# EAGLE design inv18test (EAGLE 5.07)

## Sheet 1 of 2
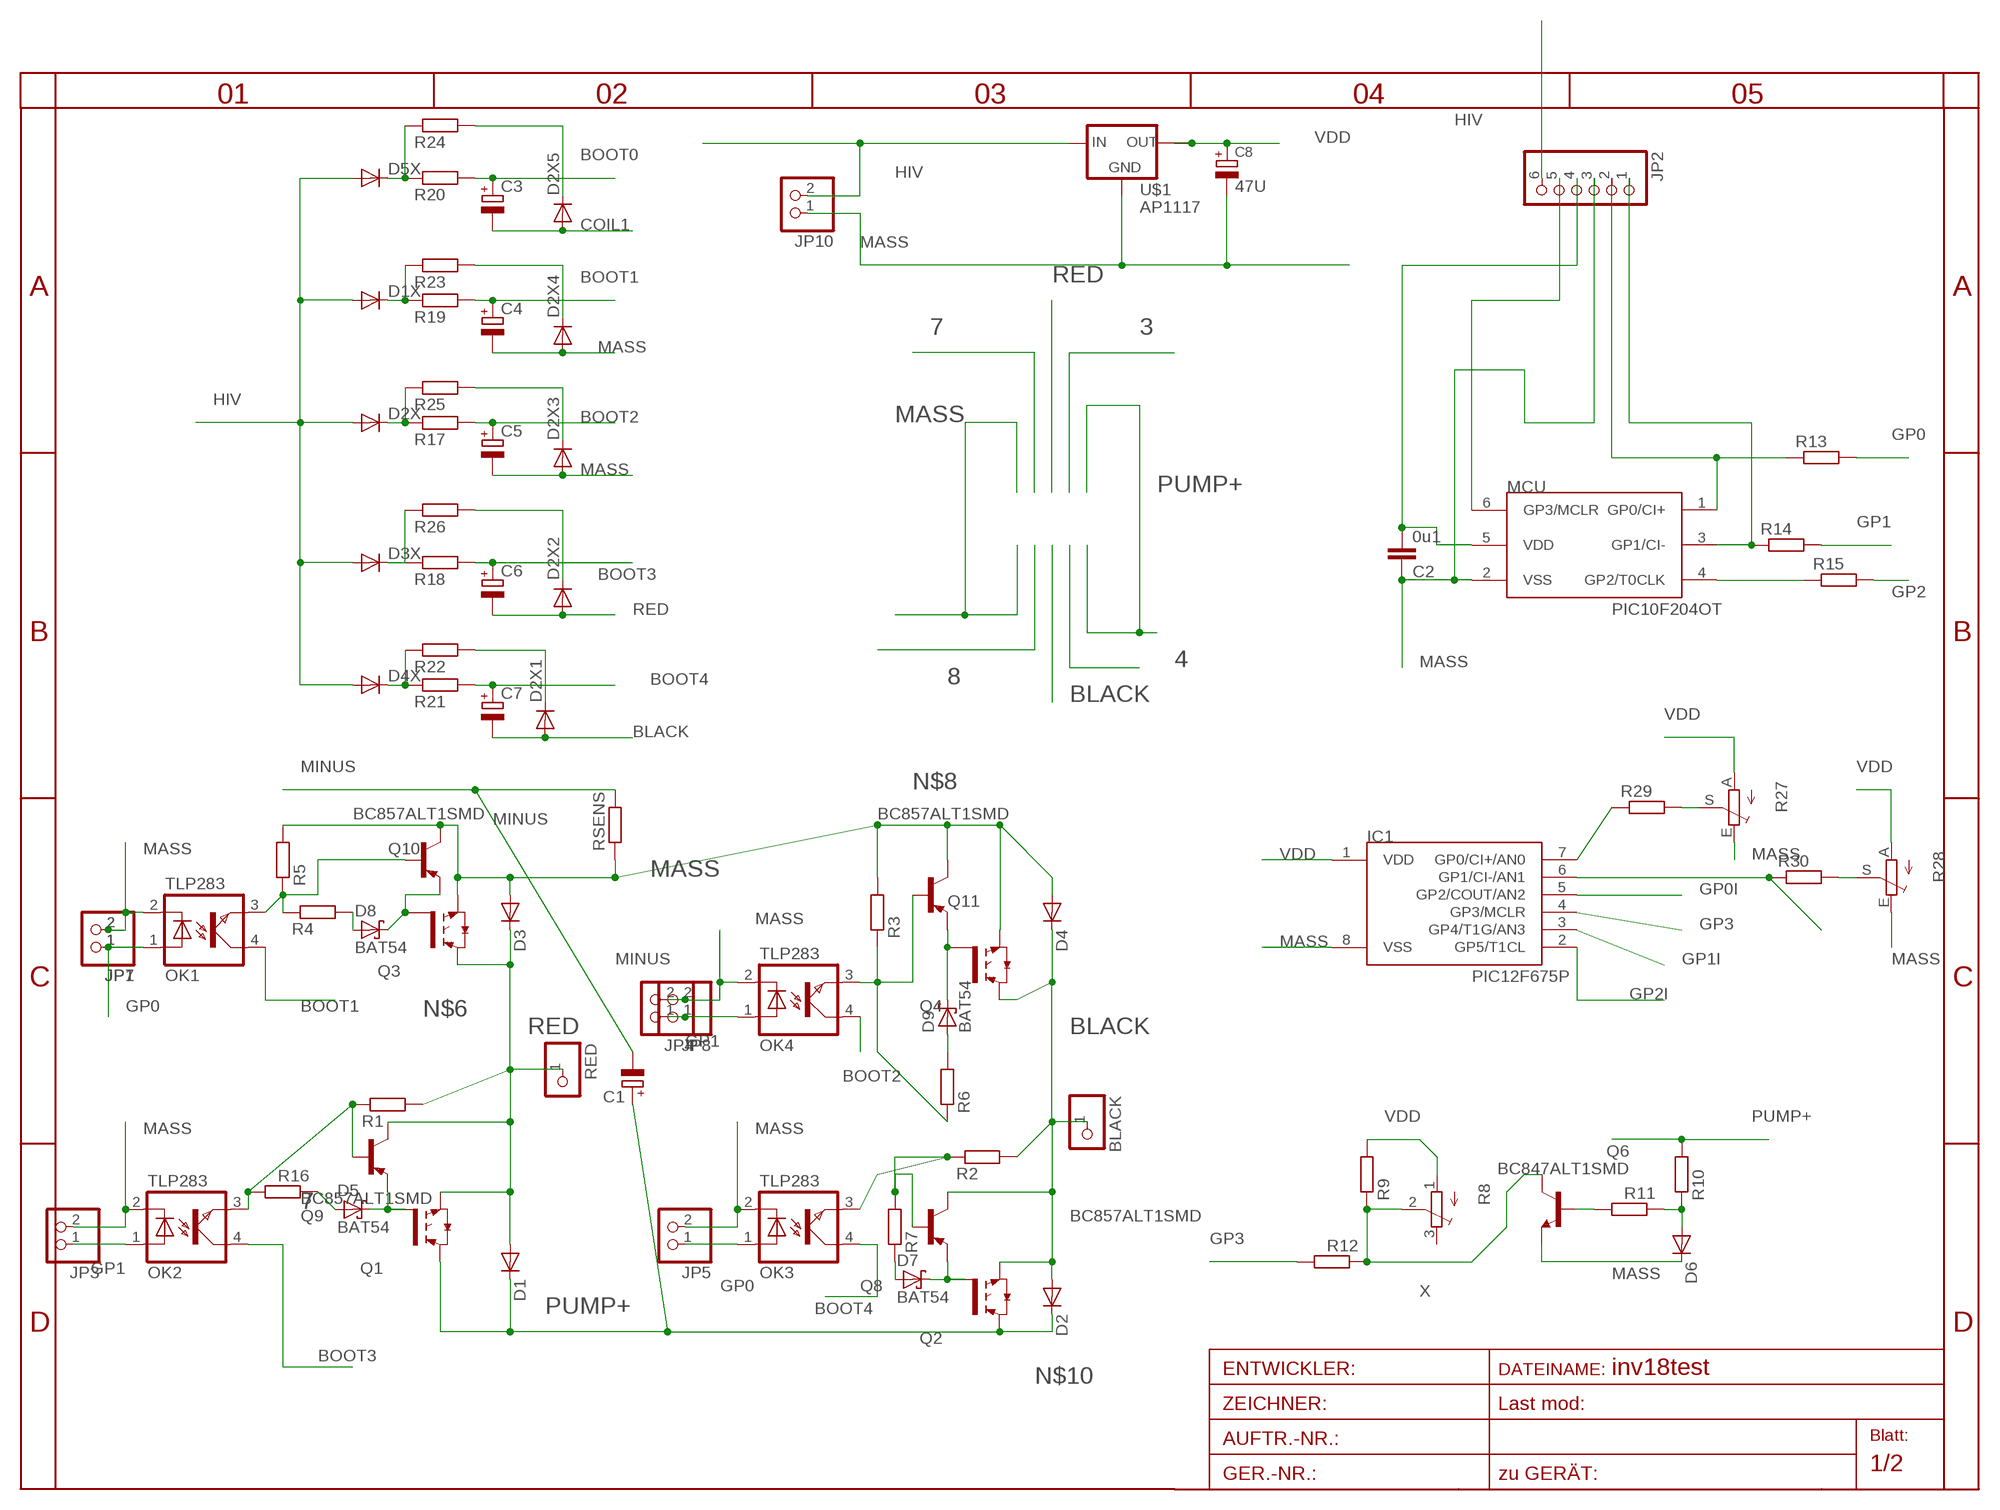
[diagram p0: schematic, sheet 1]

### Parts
BLACK  PINHD-1X14.5MM  [1X4MM5]
C1  CPOL-EUE5-13  [E5-13]
C2  0u1  C-EUC0805  [C0805]
C3  CPOL-EUC  [PANASONIC_C]
C4  CPOL-EUC  [PANASONIC_C]
C5  CPOL-EUC  [PANASONIC_C]
C6  CPOL-EUC  [PANASONIC_C]
C7  CPOL-EUC  [PANASONIC_C]
C8  47U  CPOL-EUC  [PANASONIC_C]
D1  DIODE-SMC  [SMC]
D1X  DIODE-SMA-DO214  [SMA-DO214AC]
D2  DIODE-SMC  [SMC]
D2X  DIODE-SMA-DO214  [SMA-DO214AC]
D2X1  DIODE-MINIMELF  [MINIMELF]
D2X2  DIODE-MINIMELF  [MINIMELF]
D2X3  DIODE-MINIMELF  [MINIMELF]
D2X4  DIODE-MINIMELF  [MINIMELF]
D2X5  DIODE-MINIMELF  [MINIMELF]
D3  DIODE-SMC  [SMC]
D3X  DIODE-SMA-DO214  [SMA-DO214AC]
D4  DIODE-SMC  [SMC]
D4X  DIODE-SMA-DO214  [SMA-DO214AC]
D5  BAT54  [SOT23]
D5X  DIODE-SMA-DO214  [SMA-DO214AC]
D6  DIODE-MINIMELF  [MINIMELF]
D7  BAT54  [SOT23]
D8  BAT54  [SOT23]
D9  BAT54  [SOT23]
IC1  PIC12F675P  [DIL8]
JP1  PINHD-1X2STR  [1X02]
JP2  PINHD-1X6  [1X06BOX]
JP3  PINHD-1X2STR  [1X02]
JP4  PINHD-1X2STR  [1X02]
JP5  PINHD-1X2STR  [1X02]
JP7  PINHD-1X2STR  [1X02]
JP8  PINHD-1X2STR  [1X02]
JP10  PINHD-1X2STR  [1X02]
MCU  PIC10F204OT  [SOT23-6]
OK1  TLP283  [MINI-FLAT-4]
OK2  TLP283  [MINI-FLAT-4]
OK3  TLP283  [MINI-FLAT-4]
OK4  TLP283  [MINI-FLAT-4]
Q1  IRG4BC15UD-S  [D2PACK]
Q2  IRG4BC15UD-S  [D2PACK]
Q3  IRG4BC15UD-S  [D2PACK]
Q4  IRG4BC15UD-S  [D2PACK]
Q6  BC847ALT1SMD  [SOT23]
Q8  BC857ALT1SMD  [SOT23-BEC]
Q9  BC857ALT1SMD  [SOT23-BEC]
Q10  BC857ALT1SMD  [SOT23-BEC]
Q11  BC857ALT1SMD  [SOT23-BEC]
R1  R-EU_R1206  [R1206]
R2  R-EU_R1206  [R1206]
R3  R-EU_R1206  [R1206]
R4  R-EU_R1206  [R1206]
R5  R-EU_R1206  [R1206]
R6  R-EU_R1206  [R1206]
R7  R-EU_R1206  [R1206]
R8  TRIM_EU-3223W  [3223W]
R9  R-EU_R1206  [R1206]
R10  R-EU_R1206  [R1206]
R11  R-EU_R1206  [R1206]
R12  R-EU_R1206  [R1206]
R13  R-EU_R0805  [R0805]
R14  R-EU_0207/10  [0207/10]
R15  R-EU_R0805  [R0805]
R16  R-EU_R1206  [R1206]
R17  R-EU_R1206  [R1206]
R18  R-EU_R1206  [R1206]
R19  R-EU_R1206  [R1206]
R20  R-EU_R1206  [R1206]
R21  R-EU_R1206  [R1206]
R22  R-EU_R1206  [R1206]
R23  R-EU_R1206  [R1206]
R24  R-EU_R1206  [R1206]
R25  R-EU_R1206  [R1206]
R26  R-EU_R1206  [R1206]
R27  TRIM_EU-RAND160  [RANDL]
R28  TRIM_EU-RAND160  [RANDL]
R29  R-EU_0207/30  [0207/30]
R30  R-EU_R0805  [R0805]
RED  PINHD-1X14.5MM  [1X4MM5]
RSENS  R-EU_CERAM50  [CERAM50]
U$1  AP1117  [SOT223]

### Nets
3: OK1.3(EMIT) Q10.B R4.1 R5.1
4: OK3.3(EMIT) Q8.B R2.1 R7.2
7: OK2.3(EMIT) Q9.B R1.1 R16.2
BLACK: BLACK.1 C7.- D2.A D2X1.A D4.C Q2.3(E) Q4.2(C) Q8.C R2.2
BOOT0: C3.+ R20.2 ; also sheet 2
BOOT1: C4.+ OK1.4(COL) R19.2
BOOT2: C5.+ OK4.4(COL) R17.2
BOOT3: C6.+ OK2.4(COL) R18.2
BOOT4: C7.+ OK3.4(COL) R21.2
COIL1: C3.- D2X5.A ; also sheet 2
GP0: JP1.1 JP5.1 JP7.1 OK1.1(A) OK3.1(A) R13.2
GP0I: IC1.5(GP2/COUT/AN2) JP2.2 MCU.1(GP0/CI+) R13.1
GP1: JP3.1 JP4.1 JP8.1 OK2.1(A) OK4.1(A) R14.2
GP1I: IC1.3(GP4/T1G/AN3) JP2.1 MCU.3(GP1/CI-) R14.1
GP2: R15.2 ; also sheet 2
GP2I: IC1.2(GP5/T1CL) MCU.4(GP2/T0CLK) R15.1
GP3: IC1.4(GP3/MCLR) JP2.5 MCU.6(GP3/MCLR) R12.2
HIV: D1X.A D2X.A D3X.A D4X.A D5X.A JP2.6 JP10.2 U$1.3(IN) ; also sheet 2
MASS: C2.1 C4.- C5.- C8.- D2X3.A D2X4.A D3.A D4.A D6.C IC1.8(VSS) JP1.2 JP2.3 JP3.2 JP4.2 JP5.2 JP7.2 JP8.2 JP10.1 MCU.2(VSS) OK1.2(C) OK2.2(C) OK3.2(C) OK4.2(C) Q3.3(E) Q4.3(E) Q6.2(E) Q10.C Q11.C R3.2 R5.2 R27.E R28.E RSENS.1 U$1.1(GND) ; also sheet 2
MINUS: C1.- RSENS.2 ; also sheet 2
N$2: D8.1(A) R4.2
N$4: D6.A R10.1 R11.1
N$5: Q6.1(B) R11.2
N$6: D8.3(C) Q3.1(G) Q10.E
N$7: D9.3(C) Q4.1(G) Q11.E
N$8: OK4.3(EMIT) Q11.B R3.1 R6.1
N$9: D9.1(A) R6.2
N$10: D7.3(C) Q2.1(G) Q8.E
N$11: D7.1(A) R7.1
N$12: D5.1(A) R16.1
N$13: D3X.K(C) R18.1 R26.1
N$14: D5.3(C) Q1.1(G) Q9.E
N$15: D4X.K(C) R21.1 R22.1
N$16: D2X.K(C) R17.1 R25.1
N$17: D1X.K(C) R19.1 R23.1
N$18: D5X.K(C) R20.1 R24.1
N$19: D2X1.C R22.2
N$20: D2X5.C R24.2
N$21: D2X4.C R23.2
N$22: D2X2.C R26.2
N$23: D2X3.C R25.2
N$24: R28.S R30.2
N$31: IC1.6(GP1/CI-/AN1) R30.1
N$34: R27.S R29.2
N$35: IC1.7(GP0/CI+/AN0) R29.1
PUMP+: C1.+ D1.C D2.C Q1.2(C) Q2.2(C) R10.2 ; also sheet 2
RED: C6.- D1.A D2X2.A D3.C Q1.3(E) Q3.2(C) Q9.C R1.2 RED.1
VDD: C2.2 C8.+ IC1.1(VDD) JP2.4 MCU.5(VDD) R8.1(A) R9.2 R27.A R28.A U$1.2(OUT) U$1.4(TAB)
X: Q6.3(C) R8.2(S) R9.1 R12.1
Unconnected: R8.3(E)

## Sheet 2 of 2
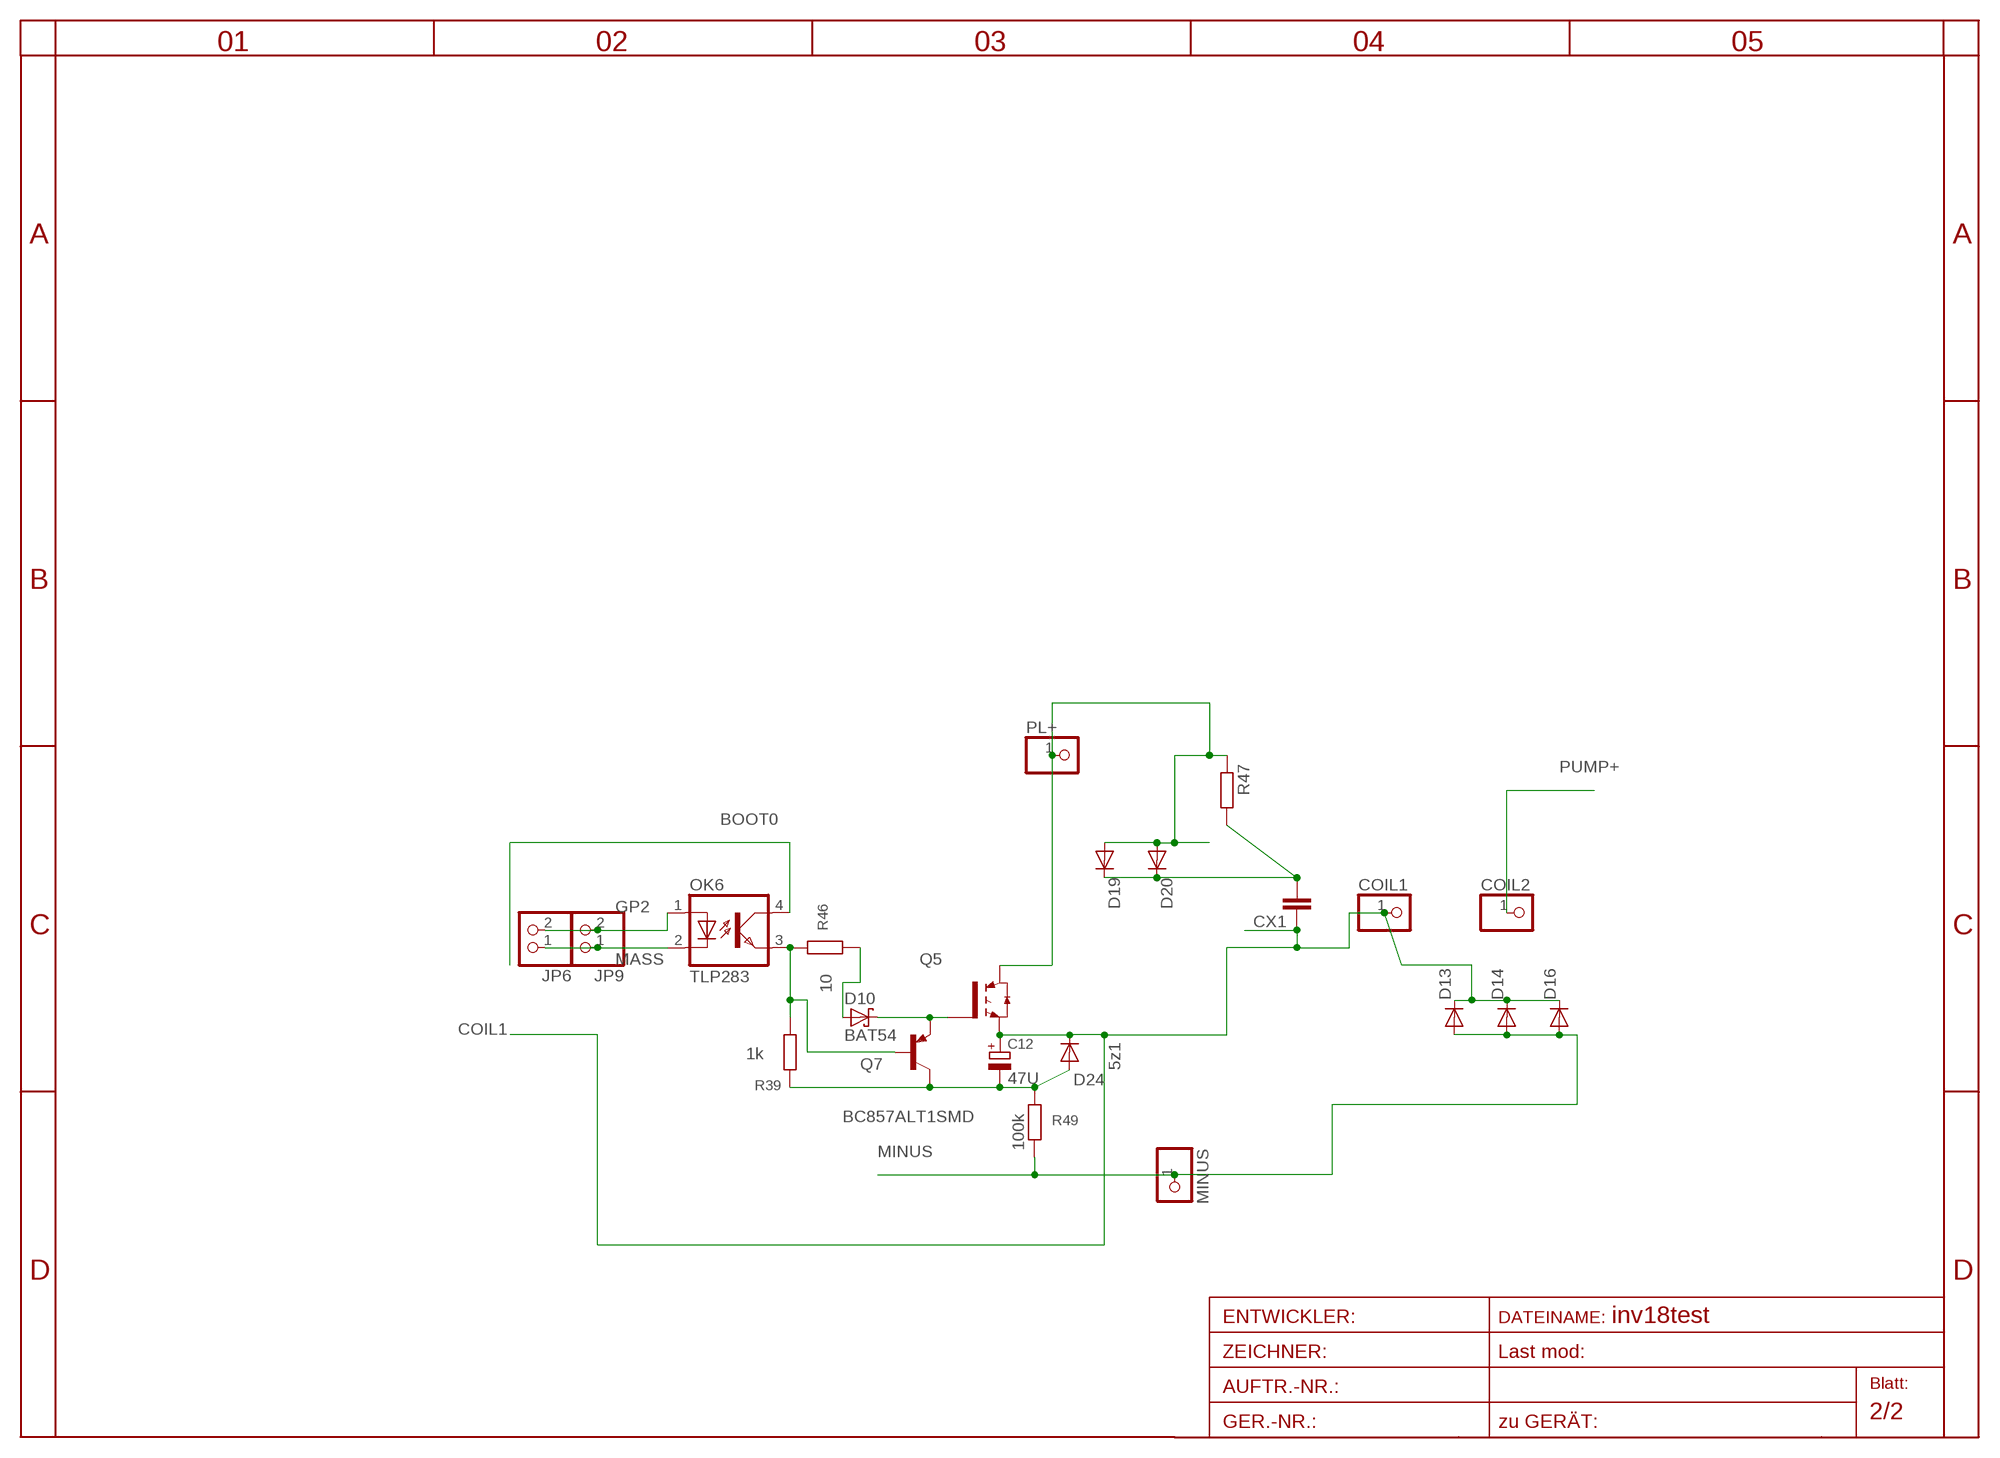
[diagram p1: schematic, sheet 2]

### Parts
C12  47U  CPOL-EUC  [PANASONIC_C]
COIL1  PINHD-1X14.5MM  [1X4MM5]
COIL2  PINHD-1X14.5MM  [1X4MM5]
CX1  CXXC22B10  [XC22B10]
D10  BAT54  [SOT23]
D13  DIODE-SMC  [SMC]
D14  DIODE-SMC  [SMC]
D16  DIODE-SMC  [SMC]
D19  DIODE-SMC  [SMC]
D20  DIODE-SMC  [SMC]
D24  5z1  DIODE-MINIMELF  [MINIMELF]
JP6  PINHD-1X2STR  [1X02]
JP9  PINHD-1X2STR  [1X02]
MINUS  PINHD-1X14.5MM  [1X4MM5]
OK6  TLP283  [MINI-FLAT-4]
PL+  PINHD-1X14.5MM  [1X4MM5]
Q5  IRG4BC15UD-S  [D2PACK]
Q7  BC857ALT1SMD  [SOT23-BEC]
R39  1k  R-EU_R1206  [R1206]
R46  10  R-EU_R1206  [R1206]
R47  R-EU_0207/5V  [0207/5V]
R49  100k  R-EU_R1206  [R1206]

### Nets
BATT-: C12.- D24.A Q7.C R39.1 R49.2
BOOT0: OK6.4(COL) ; also sheet 1
COIL1: C12.+ COIL1.1 CX1.1 D13.C D14.C D16.C D24.C Q5.3(E) ; also sheet 1
GP2: JP6.2 JP9.2 OK6.1(A) ; also sheet 1
HIV: D19.A D20.A PL+.1 Q5.2(C) R47.1 ; also sheet 1
MASS: JP6.1 JP9.1 OK6.2(C) ; also sheet 1
MINUS: D13.A D14.A D16.A MINUS.1 R49.1 ; also sheet 1
N$1: D10.3(C) Q5.1(G) Q7.E
N$3: D10.1(A) R46.1
N$43: OK6.3(EMIT) Q7.B R39.2 R46.2
PUMP+: COIL2.1 ; also sheet 1
SNUB: CX1.2 D19.C D20.C R47.2

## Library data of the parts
BLACK COIL1 COIL2 MINUS PL+ RED = pinhead:PINHD-1X1: PIN HEADER
C1 C3-C7 = rcl:CPOL-EU: POLARIZED CAPACITOR, European symbol
C2 = rcl:C-EU: CAPACITOR, European symbol
C8 C12 = rcl-2:CPOL-EU: POLARIZED CAPACITOR, European symbol
CX1 = rcl:CX: X CAPACITOR
D1 D1X D2 D2X D2X1-D2X5 D3 D3X D4 D4X D5X D6 D13 D14 D16 D19 D20 D24 = diode:DIODE-: DIODE
D5 D7-D10 = diode:BAT54: Schottky Diodes
IC1 = microchip-5:PIC12F6*: uPC nW 1k Program Flash memory 2x Timer Comparator 10b A/D converter/ 4xIN
JP1 JP3-JP10 = pinhead:PINHD-1X2: PIN HEADER
JP2 = pinhead:PINHD-1X6: PIN HEADER
MCU = microchip-3:PIC10F2*: uPC nW 0,25/0,5k Program Flash memory Comparator
OK1-OK4 OK6 = optocoupler:TLP283: TOSHIBA PHOTOCOUPLER GaAs IRED & PHOTO-TRANSISTOR Source: http://www.semicon.toshiba.co.jp/td/en/Opto/Photocoupler/en_20050928_TLP283_datasheet.pdf
Q1-Q5 = transistor-power:IRG4BC15UD-: INSULATED GATE BIPOLAR TRANSISTOR WITH ULTRAFAST SOFT RECOVERY DIODE
Q6 = transistor-npn:BC847*: NPN Transistor
Q7-Q11 = transistor-pnp:BC857*: PNP Transistror
R1-R7 R9-R12 R16-R26 R47 RSENS = rcl:R-EU_: RESISTOR, European symbol
R8 R27 R28 = pot:TRIM_EU-: POTENTIOMETER
R13-R15 R29 R30 R39 R46 R49 = rcl-2:R-EU_: RESISTOR, European symbol
U$1 = v-reg:AP1117

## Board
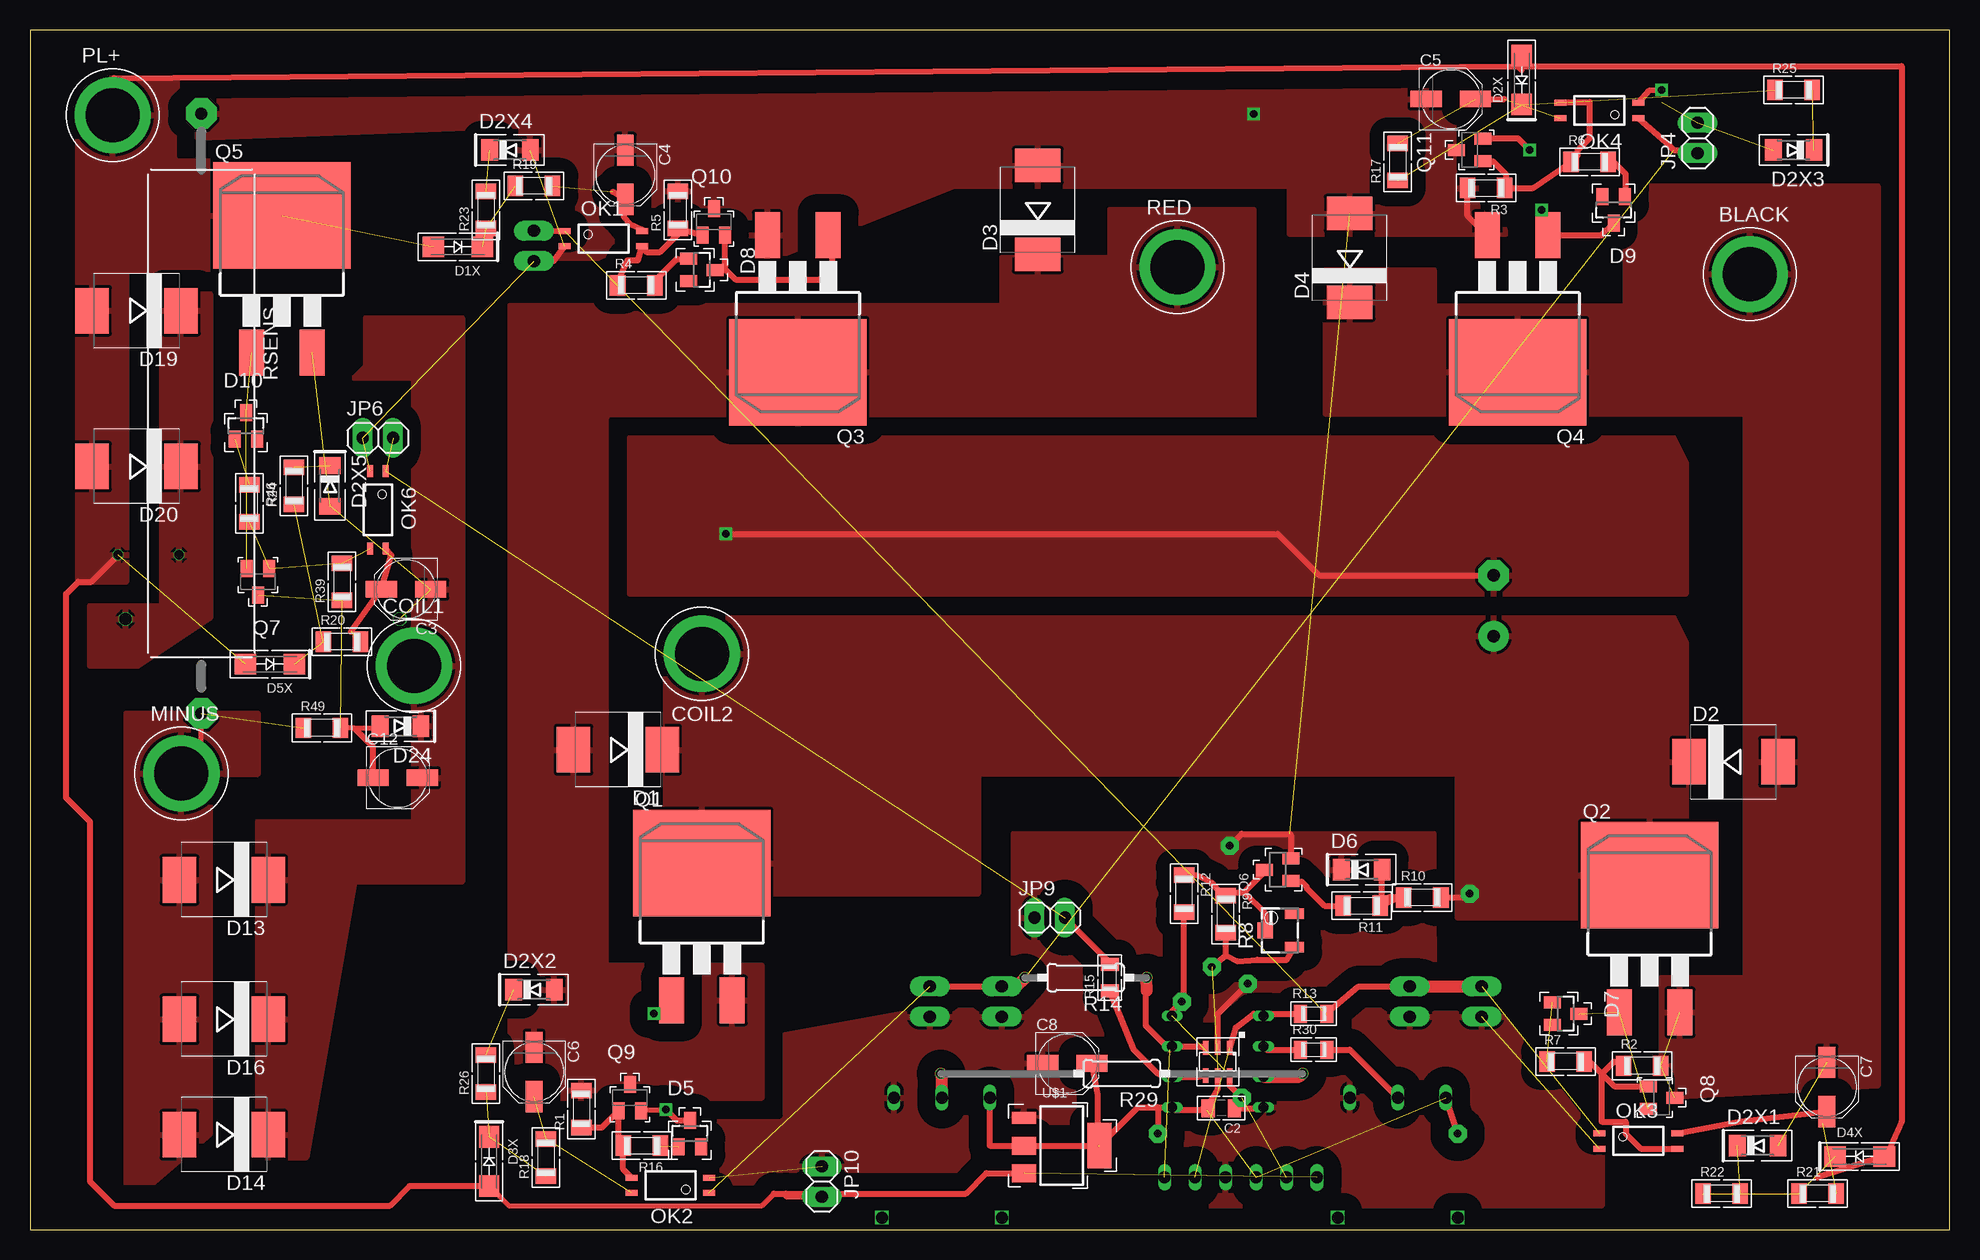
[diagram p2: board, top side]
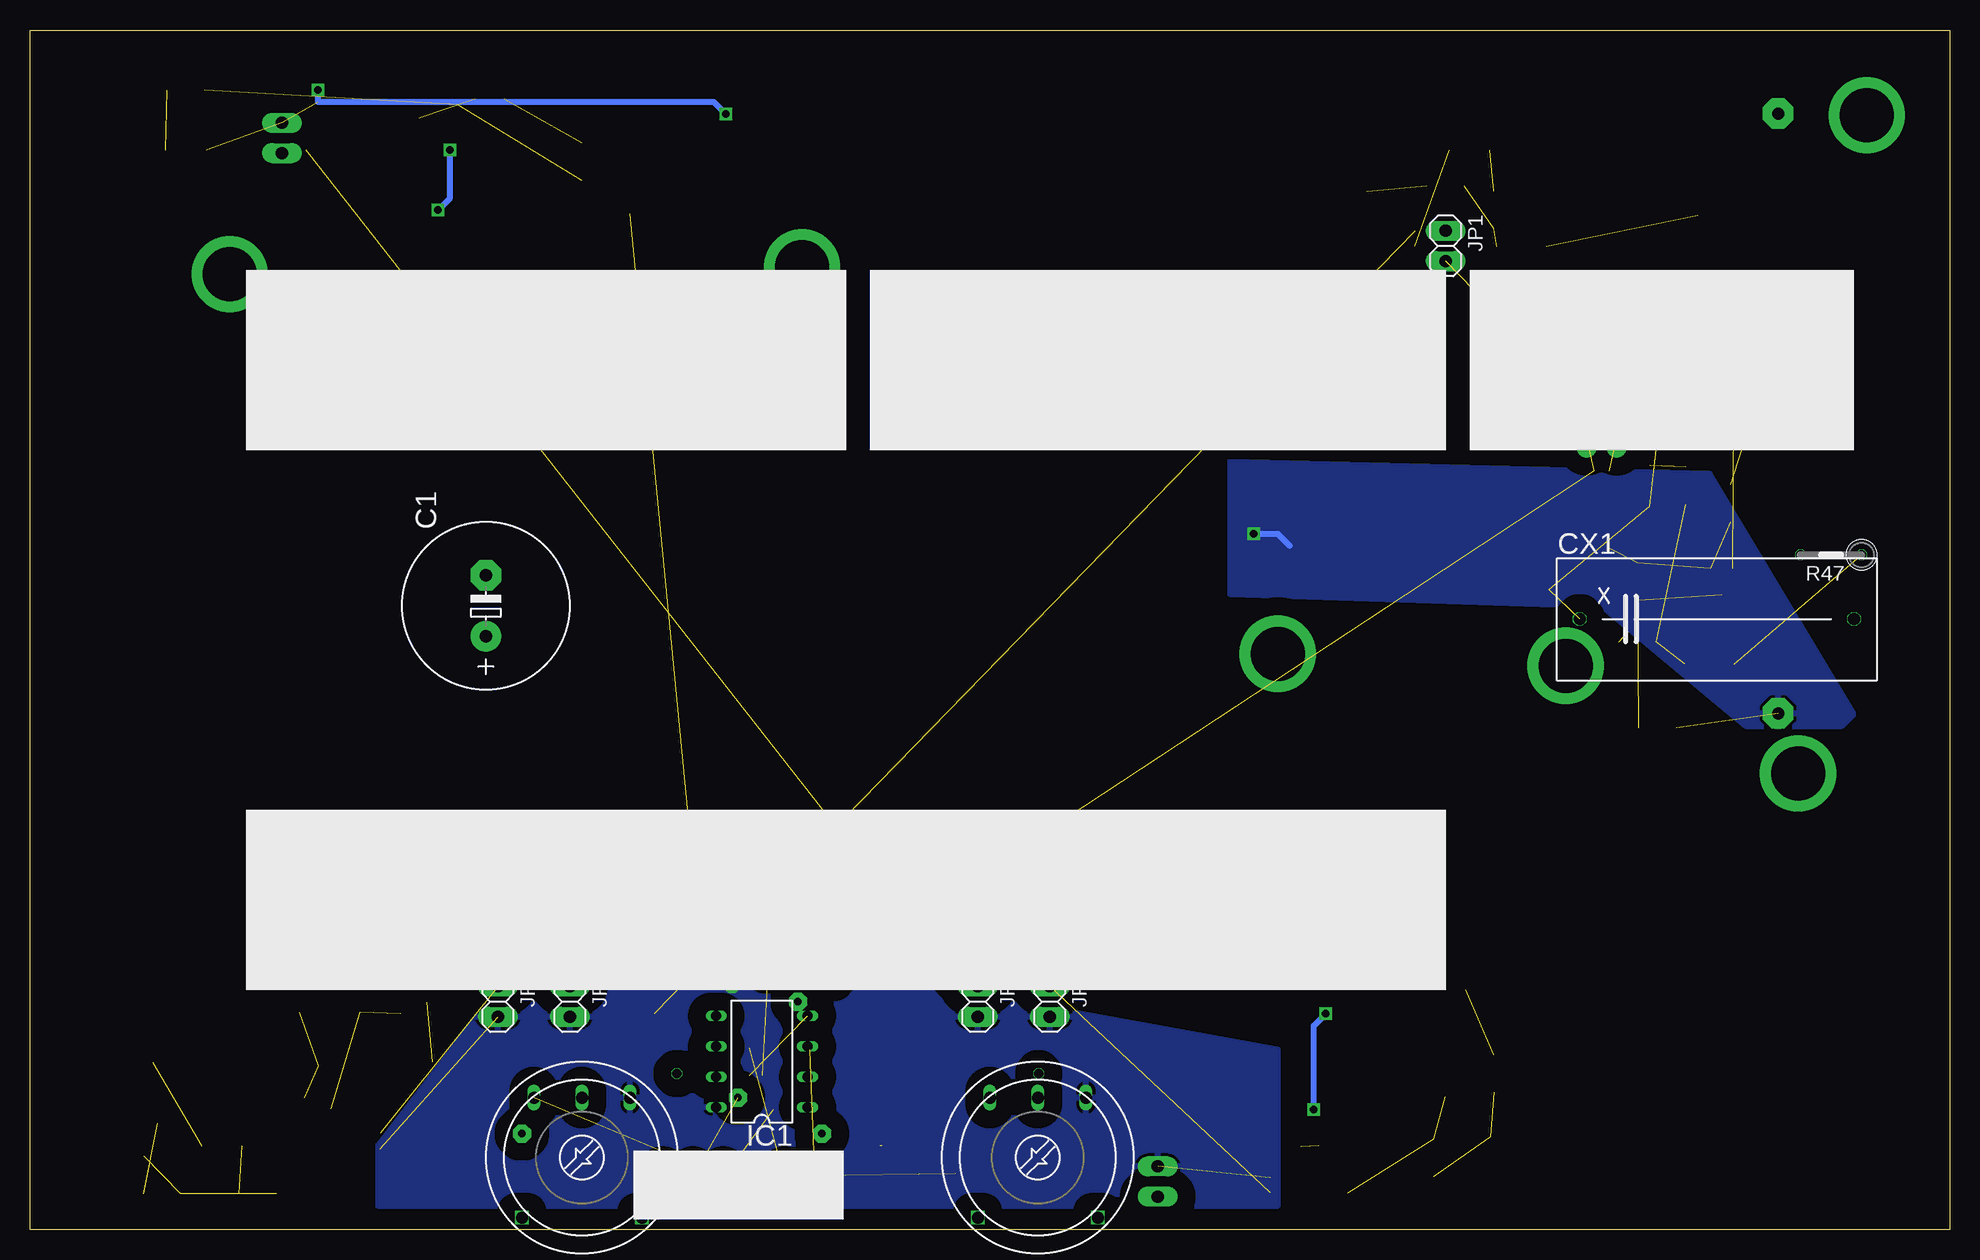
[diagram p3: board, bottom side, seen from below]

Size 160 x 100 mm. Coordinates in mm from the lower left corner, seen from the top.
Outline: 0,0 160,0 160,100 0,100 0,0
Copper layers (1*16): Top 0.035mm / dielectric 1.5mm / Bottom 0.035mm
Design rules "default": minimum track width 10mil, minimum drill 20mil, track to track 8mil, track to pad 8mil, pad to pad 8mil, via to via 8mil, smd to smd 8mil, copper to edge 40mil, drill to drill 8mil, minimum pad ring 1mil, minimum via ring 8mil, stop-mask expansion 4mil, vias tented up to drill 0mil, thermal gap 10mil

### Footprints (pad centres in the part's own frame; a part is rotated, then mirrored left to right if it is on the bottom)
1X4MM5 = drill 4.5 pad 6.35 round: 1 0,0
E5-13 = drill 1.016 pad 2.54 round: + -2.54,0 | drill 1.016 pad 2.54 octagon: - 2.54,0
C0805 = smd 1.1 x 1.5: 1 -1.1,0; 2 1.1,0
PANASONIC_C = smd 2.6 x 1.4: + 2.05,0; - -2.05,0
XC22B10 = drill 1.016 octagon: 1 -11.43,0.025; 2 11.43,0.025
SMC = smd 2.8 x 3.8: A 3.7,0; C -3.7,0
SMA-DO214AC = smd 1.8 x 1.7: A 2.05,-0.127; K -2.05,-0.127
MINIMELF = smd 1.4 x 1.8: A 1.7,0; C -1.7,0
SOT23 = smd 1 x 1.4: 1 -0.95,-1.1; 2 0.95,-1.1; 3 0,1.1
DIL8 = drill 0.8 long: 1 -3.81,-3.81; 2 -1.27,-3.81; 3 1.27,-3.81; 4 3.81,-3.81; 5 3.81,3.81; 6 1.27,3.81; 7 -1.27,3.81; 8 -3.81,3.81
1X02 = drill 1.016 pad 1.676 long: 1 -1.27,0; 2 1.27,0
1X06BOX = drill 1 long: 1 -6.35,0; 2 -3.81,0; 3 -1.27,0; 4 1.27,0; 5 3.81,0 | drill 1.016 long: 6 6.35,0
SOT23-6 = smd 0.45 x 1.2: 1 -1.016,-1.15; 2 0,-1.15; 3 1.016,-1.15; 4 1.016,1.15; 5 0,1.15; 6 -1.016,1.15
MINI-FLAT-4 = smd 1 x 0.5: 1 -3.24,0.635; 2 -3.24,-0.635; 3 3.24,-0.635; 4 3.24,0.635
D2PACK = smd 2.083 x 3.81: 1 -2.54,-8.89; 3 2.54,-8.89 | smd 11.43 x 8.89: 2 0,2.54
SOT23-BEC = smd 1 x 1.4: B -0.95,-1.1; C 0,1.1; E 0.95,-1.1
R1206 = smd 1.3 x 1.7: 1 -1.55,0; 2 1.55,0
3223W = smd 0.9 x 1.6: 1 -1.4,-1.215; 3 1.4,-1.215 | smd 1.3 x 1.3: 2 0,1.215
R0805 = smd 1.1 x 1.5: 1 -1.1,0; 2 1.1,0
0207/10 = drill 0.813 octagon: 1 -5.08,0; 2 5.08,0
RANDL = drill 1 long: A -4,5; E 4,5; S 0,5 | drill 1 square: P$1 -5,-5; P$2 5,-5
0207/30 = drill 0.813 octagon: 1 -15.08,0; 2 15.08,0
0207/5V = drill 0.813 octagon: 1 -2.54,0; 2 2.54,0
CERAM50 = drill 1 pad 2.54 octagon: 1 -25,0; 2 25,0
SOT223 = smd 1 x 2: 1 -2.3,-3.15 | smd 1.5 x 2: 2 0,-3.15; 3 2.3,-3.15 | smd 3.8 x 2: 4 0,3.15

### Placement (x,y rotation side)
BLACK  143.35,79.64 0 top
C1  122,52 90 bottom
C2  99.3,10.12 180 top
C3  31.34,53.37 180 top
C4  49.62,87.92 270 top
C5  118.43,94.25 0 top
C6  42.02,13.13 270 top
C7  149.78,11.89 270 top
C8  86.46,13.85 0 top
C12  30.65,37.66 0 top
COIL1  32,47 0 top
COIL2  56,48 180 top
CX1  19.39,50.87 0 bottom
D1  49,40 180 top
D1X  35.66,81.79 180 top
D2  142,39 0 top
D2X  124.22,95.83 90 top
D2X1  144,7 0 top
D2X2  42,20 0 top
D2X3  147,90 180 top
D2X4  40,90 0 top
D2X5  25,62 270 top
D3  84,85 90 top
D3X  38.4,5.68 270 top
D4  110,81 90 top
D4X  152.51,6.22 0 top
D5  55,8 0 top
D5X  20,47 180 top
D6  111,30 0 top
D7  128,18 270 top
D8  56,80 270 top
D9  132,85 180 top
D10  18,67 0 top
D13  16.16,29.15 180 top
D14  16.16,7.91 180 top
D16  16.16,17.53 180 top
D19  8.88,76.59 180 top
D20  8.88,63.62 180 top
D24  30.89,41.96 180 top
IC1  99,14 90 bottom
JP1  42,82 270 bottom
JP2  100.93,4.35 180 bottom
JP3  75,19 270 bottom
JP4  139,91 90 top
JP5  121,19 270 bottom
JP6  29,66 0 top
JP7  115,19 270 bottom
JP8  81,19 270 bottom
JP9  85,26 0 top
JP10  66,4 270 top
MCU  99,14 180 top
MINUS  12.62,38.02 0 top
OK1  47.8,82.6 0 top
OK2  53.38,3.68 180 top
OK3  134.06,7.38 0 top
OK4  130.81,93.29 180 top
OK6  29,60 270 top
PL+  6.89,92.9 0 top
Q1  56,28 0 top
Q2  135,27 0 top
Q3  64,74 180 top
Q4  124,74 180 top
Q5  21,82 0 top
Q6  104,30 90 top
Q7  19,54 180 top
Q8  136,11 270 top
Q9  50,11 0 top
Q10  57,84 0 top
Q11  120,90 90 top
R1  45.95,10.05 90 top
R2  134.38,13.65 0 top
R3  121.38,86.83 180 top
R4  50.53,78.71 0 top
R5  54,85 90 top
R6  130,89 0 top
R7  128,14 0 top
R8  104.18,24.94 90 top
R9  99.67,26.3 270 top
R10  116.05,27.67 0 top
R11  111,27 180 top
R12  96.2,28 270 top
R13  107,18 0 top
R14  88,21 180 top
R15  90,21 90 top
R16  51,7 180 top
R17  114,89 90 top
R18  43,6 90 top
R19  42,87 0 top
R20  26,49 0 top
R21  149,3 0 top
R22  141,3 0 top
R23  38,85 90 top
R24  22,62 90 top
R25  147,95 0 top
R26  38,13 90 top
R27  76,6 0 bottom
R28  114,6 0 bottom
R29  91,13 180 top
R30  107,15 0 top
R39  26,54 90 top
R46  18.28,60.54 270 top
R47  9.88,56.24 180 bottom
R49  24.34,41.81 0 top
RED  95.65,80.23 0 top
RSENS  14.29,68.04 270 top
U$1  86,7 270 top

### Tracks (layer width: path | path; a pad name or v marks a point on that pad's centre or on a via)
3
  Top 0.5: Q10.B 54.05,83.45 R5.1 54,83 52.5,81.5 51.38,81.5 OK1.3 50.67,80.8 49.8,80.8 48.98,78.98 R4.1
4
  Top 0.5: OK3.3 134.25,6.75 133,8 133,9 131,9 131,13 | 131,13 132,14 132.48,14 R2.1 | R7.2 130,14 131,13 | Q8.B 132.05,11.95 131,13
7
  Top 0.5: R1.1 47.65,8.5 Q9.B 49.05,7.4 R16.2 49.45,5 OK2.3
BATT-  (2 unrouted)
  Top 0.406: R49.2 27,41.81 29.04,41.81 D24.A
  Top 0.5: C12.- 28.6,40.21 27,41.81
BLACK  (3 unrouted)
  pour Top (isolate 1.5, rank 2): 108,80 117,80 117,77 133,77 133,87 154,87 154,12 136,11 136,21 143,21 143,68 108,68
BOOT0  (1 unrouted)
  Top 0.5: 26.76,49.84 C3.+ 30.11,56.2 OK6.4
BOOT1  (1 unrouted)
  Top 0.5: 48.57,86.52 C4.+ 49.53,84.37 50,83.8 51,83.36 OK1.4
BOOT2  (2 unrouted)
  Top 0.5: C5.+ 122.88,94.25
BOOT3  (2 unrouted)
BOOT4  (1 unrouted)
  Top 0.5: 149.39,8.84 C7.+ 142.6,9.02 OK3.4
COIL1  (3 unrouted)
  pour Top (isolate 1.5, rank 2): 28,76 36,76 36,29 27,29 23,6 19,6 19,34 32,34 32,71 27,71 28,72
GP0  (2 unrouted)
  Top 0.5: JP1.1 43.62,83.27 OK1.1 | R13.2 108,18 110.73,20.27 JP7.1
  Top 1: JP7.1 JP5.1
GP0I  (1 unrouted)
  Top 0.5: MCU.1 100.52,16.82 102,18 102.62,18 IC1.5 103,18 R13.1
GP1  (2 unrouted)
  Top 0.5: OK4.1 136.34,90.66 137,90 138.73,90 JP4.1 | 82.19,20.27 JP8.1 JP3.1
  Top 1: 82.19,20.27 R14.2
GP1I  (1 unrouted)
  Top 0.5: MCU.3 97.6,15.27 IC1.3 95,15.08 95,15 93,17 93,19.9 93.1,19.9
  Top 1: 93.1,19.9 R14.1
GP2  (2 unrouted)
  Top 0.5: R15.2 89.9,22.37 JP9.2
GP2I
  Top 0.5: R15.1 92,15 94,13 94.92,13 IC1.2 97.36,12.73 MCU.4
GP3  (via drill 0.6 pad 1.5)  (2 unrouted)
  Top 0.5: MCU.6 100.02,11.98 v101,11 | R12.2 96.2,19.2 v96,19 95.19,18.19 IC1.4
HIV  (3 unrouted)
  Top 0.406: 62,3 61,2 39.9,2 D3X.A | JP10.2 63,2.73 63,3
  Top 0.5: 124,97 156,97 156,9 154.44,5.44 D4X.A 149,4.35 | 7,96 124,97 | D2X.A 124.35,96.65 124,97 | D3X.A 31.63,3.63 30,2 7,2 5,4 5,34 3,36 3,53 4,54 5.1,54 R47.1 | U$1.3 79.7,4.7 78,3 63,3 62,3
  pour Top (isolate 1.5, rank 2): 4,96 17,96 17,80 8,80 8,54 4,54
MASS  (via drill 0.6, 0.6 pad 1.5)  (8 unrouted)
  Top 0.5: OK4.2 134.93,94.92 v136,95 | JP1.2 43.66,80.73 OK1.2 | R3.2 119.83,84.52 Q4.3 | C2.1 102.74,10.12 IC1.8 | MCU.2 99,18 v101.5,20.5 | Q6.2 105.1,32.9 105,33 101,33 v100,32
  Bottom 0.5: v136,95 136,94 103,94 v102,93
  pour Top (isolate 1.5): 14,95 118,97 123,83 105,83 105,87 77,87 62,81 44,81 40,82 41,92 14,91
  pour Top (isolate 1.5, rank 3): 82,33 117,33 117,20 121,20 131,7 131,2 56,2 56,15 78,19 82,22
  pour Bottom (isolate 1.5, rank 3): 82,33 117,33 117,20 121,20 131,7 131,2 56,2 56,15 78,19 82,22
MINUS  (via drill 0.6)  (1 unrouted)
  Top 0.406: RSENS.2 14.29,39.69 MINUS.1
  Top 0.5: C1.- 107.46,54.54 104,58 v58,58
  Bottom 0.5: v58,58 56,58 55,57
  pour Top (isolate 1.5): 138,53 50,53 50,66 137,66 138,64
  pour Top (isolate 1.5, rank 3): 8,43 8,2 15,8 15,38 19,38 19,43
  pour Bottom (isolate 1.5, rank 2): 8,43 20,63 60,64 60,53 29,52 17,42 9,42
N$1  (2 unrouted)
N$2
  Top 0.5: R4.2 51.71,78.71 53.9,80.9 54.85,80.9 D8.1
N$3  (1 unrouted)
N$4
  Top 0.5: R10.1 113.22,27.67 114.28,27.73 | R11.1 114.28,27.73 | D6.A 112.7,27.3 114.28,27.73
N$5
  Top 0.5: R11.2 107.9,27 106.4,28.5 106.4,28.6 106,29 105.15,29 Q6.1
N$6
  Top 0.5: 57.6,80 58,80 58.8,79.2 65.8,79.2 66.9,80.3 66.9,82.53 Q3.1 | D8.3 57.6,80 | Q10.E 57.95,80.35 57.6,80
N$7  (via drill 0.6)
  Top 0.5: Q11.E 124.05,90.95 v125,90 | v126,85 126,83.43 Q4.1 130.99,82.89 D9.3
  Bottom 0.5: v125,90 125,86 v126,85
N$8
  Top 0.5: Q11.B 121.95,89.05 123,88 123,86.9 R3.1 125.28,86.83 R6.1 129,89.55 129,90 130,91 130,94 129.93,93.92 OK4.3
N$9
  Top 0.5: R6.2 132,89 133,88 133,86.15 D9.1
N$10  (2 unrouted)
N$11  (1 unrouted)
N$12  (1 unrouted)
N$13  (2 unrouted)
N$14  (via drill 0.6)
  Top 0.406: Q9.E 51.05,10 v53,10
  Top 0.5: D5.3 53.9,9.1 v53,10 | v52,18 52.35,18 Q1.1
  Bottom 0.5: v53,10 53,17 v52,18
N$15  (2 unrouted)
N$16  (2 unrouted)
N$17  (2 unrouted)
N$18  (2 unrouted)
N$19  (1 unrouted)
N$20  (1 unrouted)
N$21  (1 unrouted)
N$22  (1 unrouted)
N$23  (1 unrouted)
N$24
  Top 0.5: R28.S 110,15 R30.2
N$31
  Top 0.5: IC1.6 103.08,15 R30.1
N$34
  Top 1: R27.S 76,12.92 R29.2
N$35
  Top 1: IC1.7 105.81,12.73 R29.1
N$43  (3 unrouted)
PUMP+  (via drill 0.6 pad 1.5)
  Top 0.5: R10.2 119.67,27.67 v120,28
  pour Top (isolate 1.5): 138,49 138,26 119,26 119,38 79,38 79,28 53,28 53,51 137,51
RED
  pour Top (isolate 1.5, rank 2): 102,67 102,85 90,85 90,81 81,81 81,77 40,77 40,11 61,11 61,22 48,22 48,67
SNUB
  pour Top (isolate 1.5, rank 2): 11,78 15,78 15,51 9,47 5,47 5,52 11,52
VDD  (via drill 0.6 pad 1.5)  (4 unrouted)
  Top 0.5: MCU.5 99,11.7 98,10 95.38,10 IC1.1 94,10.19 | R27.A 80,7 U$1.2 89,7 89,11.24 C8.+ | U$1.4 92.34,10.19 94,10.19 | v119,8 R28.A | 94,10.19 v94,8 | 99.67,22.87 R9.2 | v98.5,21.9 99.67,22.87 | 99.67,22.87 100.63,22.37 102.3,22.5 104.75,22.5 R8.1
  Top 1: 98,10 98.08,10 C2.2
X
  Top 0.5: R8.2 102.97,26.34 101.2,28.1 | 101.2,28.1 99.92,28.1 R9.1 99.52,27.7 98.5,28.9 97.25,29.55 R12.1 | Q6.3 102.9,29.8 101.2,28.1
